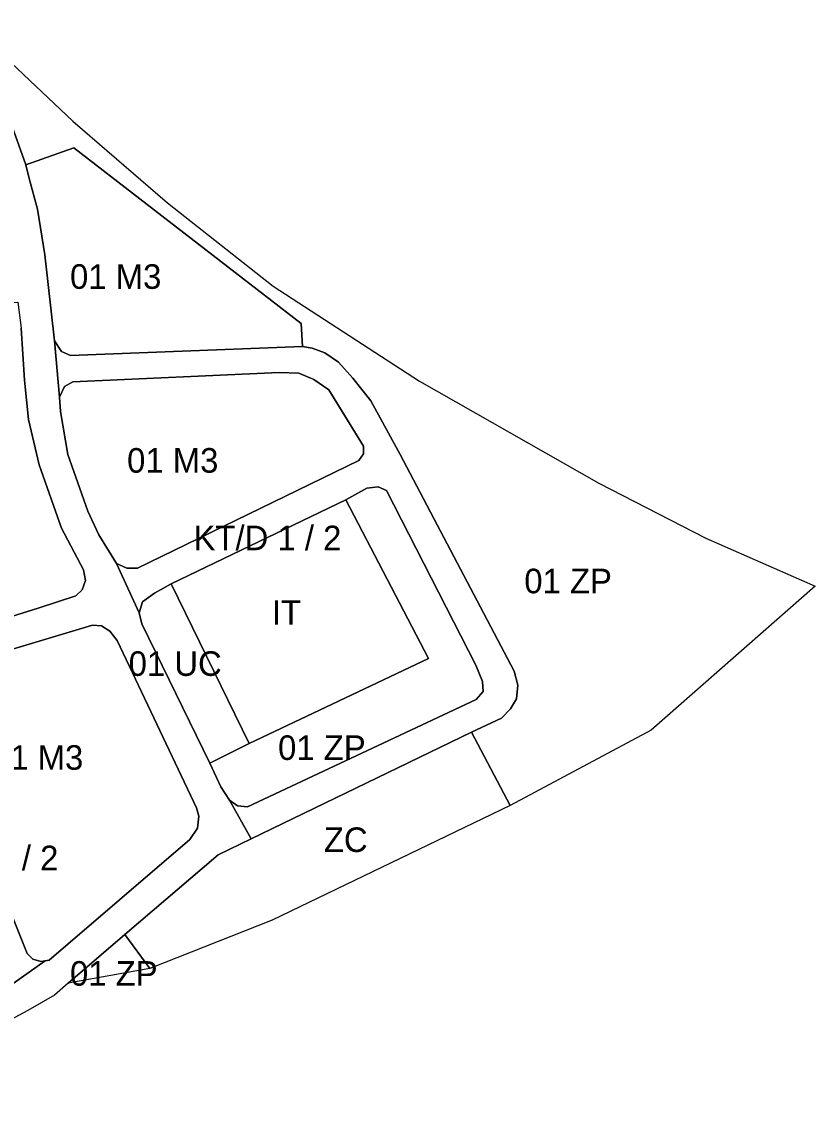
# Model space of a CAD drawing. Extents: x 7419295 to 7421535, y 5544294 to 5545394.
# Drawn here: x 7421212.4 to 7421535.3, y 5544388.6 to 5544834.1 of the extents above; entities that cross this region are included whole.
import ezdxf

# ---------------------------------------------------------------- set-up
doc = ezdxf.new("R2010")
doc.units = 0
doc.layers.add('linie_rozgraniczajace', color=7, linetype='Continuous')
doc.layers.add('oznaczenia_przeznaczen', color=7, linetype='Continuous')

msp = doc.modelspace()

# ---------------------------------------------------------------- linework, layer by layer
at = {"layer": 'linie_rozgraniczajace'}
for points in [[(7421190.2, 5544834.12), (7421233.16, 5544793.69), (7421271.62, 5544760.47), (7421314.64, 5544726.59), (7421374.27, 5544687.97), (7421447.31, 5544646.52), (7421490.78, 5544624.02), (7421535.28, 5544604.57), (7421468.56, 5544545.99), (7421411.16, 5544515.34), (7421395.36, 5544545.19), (7421407.68, 5544550.9), (7421411.34, 5544554.63), (7421413.72, 5544558.75), (7421414.29, 5544564.29), (7421412.78, 5544570.04), (7421366.31, 5544658.08), (7421354.46, 5544679.96), (7421347.09, 5544689.2), (7421341.26, 5544695.67), (7421335.7, 5544699.47), (7421330.54, 5544701.34), (7421326.62, 5544702), (7421326.08, 5544711.37), (7421233.6, 5544782.82), (7421214.02, 5544775.92), (7421200.76, 5544812.79)], [(7421200.76, 5544812.79), (7421214.02, 5544775.92), (7421215.32, 5544770.41), (7421218.69, 5544757.87), (7421221.67, 5544739.36), (7421225.6, 5544704.39), (7421227.66, 5544681.41), (7421228.05, 5544675.61), (7421231.15, 5544658.15), (7421239.24, 5544635.07), (7421243.76, 5544625.42), (7421250.91, 5544613.78), (7421260.12, 5544593.65), (7421261.25, 5544589.22), (7421288.83, 5544532.5), (7421293.35, 5544522.9), (7421296.9, 5544517.53), (7421305.77, 5544501.83), (7421292.24, 5544495.28), (7421254.34, 5544462.81), (7421231.17, 5544442.98), (7421225.65, 5544438.13), (7421214.78, 5544431.88), (7421134.24, 5544388.56)], [(7421186.73, 5544585.6), (7421218.96, 5544595.55), (7421234.34, 5544600.61), (7421236.91, 5544603.1), (7421238.34, 5544606.8), (7421237.43, 5544611.2), (7421228.5, 5544628.12), (7421219.45, 5544653.87), (7421215.06, 5544672.35), (7421213.44, 5544688.32), (7421212.1, 5544709.5)], [(7421203.12, 5544438.98), (7421221.82, 5544452.13), (7421223.48, 5544452.42), (7421280.78, 5544501.56), (7421283.93, 5544506.16), (7421284.37, 5544510.95), (7421283.44, 5544514.42), (7421251.11, 5544582.43), (7421248.25, 5544586.19), (7421244.82, 5544588.44), (7421241.15, 5544588.74), (7421193.57, 5544574.43)]]:
    msp.add_lwpolyline(points, dxfattribs=at)
for points in [[(7421214.02, 5544775.92), (7421233.6, 5544782.82), (7421326.08, 5544711.37), (7421326.62, 5544702), (7421232.2, 5544698.39), (7421228.48, 5544700.03), (7421225.6, 5544704.39), (7421221.67, 5544739.36), (7421218.69, 5544757.87), (7421215.32, 5544770.41)], [(7421210.76, 5544720.11), (7421212.1, 5544709.5), (7421213.44, 5544688.32), (7421215.06, 5544672.35), (7421219.45, 5544653.87), (7421228.5, 5544628.12), (7421237.43, 5544611.2), (7421238.34, 5544606.8), (7421236.91, 5544603.1), (7421234.34, 5544600.61), (7421218.96, 5544595.55), (7421186.73, 5544585.6), (7421170.98, 5544582.34), (7421159.54, 5544616.11), (7421149.43, 5544626.06), (7421116.42, 5544643.66), (7421034.62, 5544653.87), (7421009.98, 5544649.77), (7421000.75, 5544682.83), (7421016.84, 5544686.9), (7421014.51, 5544696.59), (7421105.89, 5544713.01)], [(7421225.6, 5544704.39), (7421228.48, 5544700.03), (7421232.2, 5544698.39), (7421326.62, 5544702), (7421330.54, 5544701.34), (7421335.7, 5544699.47), (7421341.26, 5544695.67), (7421347.09, 5544689.2), (7421354.46, 5544679.96), (7421366.31, 5544658.08), (7421412.78, 5544570.04), (7421414.29, 5544564.29), (7421413.72, 5544558.75), (7421411.34, 5544554.63), (7421407.68, 5544550.9), (7421395.36, 5544545.19), (7421305.77, 5544501.83), (7421296.9, 5544517.53), (7421300.18, 5544515.13), (7421304.25, 5544514.73), (7421397.29, 5544558.43), (7421400.18, 5544561.67), (7421399.85, 5544565.83), (7421397.2, 5544572.43), (7421360.78, 5544643.5), (7421357.38, 5544645.01), (7421352.8, 5544644.37), (7421344.25, 5544639.7), (7421273.15, 5544605.51), (7421266.31, 5544601.65), (7421261.52, 5544598.18), (7421260.12, 5544593.65), (7421250.91, 5544613.78), (7421255.12, 5544611.86), (7421259.41, 5544611.89), (7421349.52, 5544655.65), (7421351.47, 5544658.41), (7421351.46, 5544661.55), (7421337.34, 5544684.38), (7421331.29, 5544688.61), (7421325.14, 5544691.19), (7421317.18, 5544691.46), (7421233.12, 5544687.75), (7421229.7, 5544685.82), (7421227.66, 5544681.41)], [(7421227.66, 5544681.41), (7421229.7, 5544685.82), (7421233.12, 5544687.75), (7421317.18, 5544691.46), (7421325.14, 5544691.19), (7421331.29, 5544688.61), (7421337.34, 5544684.38), (7421351.46, 5544661.55), (7421351.47, 5544658.41), (7421349.52, 5544655.65), (7421259.41, 5544611.89), (7421255.12, 5544611.86), (7421250.91, 5544613.78), (7421243.76, 5544625.42), (7421239.24, 5544635.07), (7421231.15, 5544658.15), (7421228.05, 5544675.61)], [(7421344.25, 5544639.7), (7421352.8, 5544644.37), (7421357.38, 5544645.01), (7421360.78, 5544643.5), (7421397.2, 5544572.43), (7421399.85, 5544565.83), (7421400.18, 5544561.67), (7421397.29, 5544558.43), (7421304.25, 5544514.73), (7421300.18, 5544515.13), (7421296.9, 5544517.53), (7421293.35, 5544522.9), (7421288.83, 5544532.5), (7421304.87, 5544540.61), (7421377.86, 5544575.17)], [(7421344.25, 5544639.7), (7421377.86, 5544575.17), (7421304.87, 5544540.61), (7421273.15, 5544605.51)], [(7421273.15, 5544605.51), (7421304.87, 5544540.61), (7421288.83, 5544532.5), (7421261.25, 5544589.22), (7421260.12, 5544593.65), (7421261.52, 5544598.18), (7421266.31, 5544601.65)], [(7421173.61, 5544569.95), (7421177.84, 5544571.46), (7421193.57, 5544574.43), (7421241.15, 5544588.74), (7421244.82, 5544588.44), (7421248.25, 5544586.19), (7421251.11, 5544582.43), (7421283.44, 5544514.42), (7421284.37, 5544510.95), (7421283.93, 5544506.16), (7421280.78, 5544501.56), (7421223.48, 5544452.42), (7421221.82, 5544452.13), (7421220.16, 5544451.84), (7421216.79, 5544452.75), (7421214.51, 5544455.18), (7421170.83, 5544563.87), (7421171.32, 5544567.47)], [(7421173.61, 5544569.95), (7421171.32, 5544567.47), (7421170.83, 5544563.87), (7421214.51, 5544455.18), (7421216.79, 5544452.75), (7421220.16, 5544451.84), (7421221.82, 5544452.13), (7421203.12, 5544438.98), (7421206.52, 5544445.23), (7421205.58, 5544449), (7421163.14, 5544554.61), (7421160.48, 5544561.63), (7421157.65, 5544564.79), (7421156.21, 5544565.11)], [(7421395.36, 5544545.19), (7421411.16, 5544515.34), (7421314.26, 5544468.66), (7421264.47, 5544448.95), (7421254.34, 5544462.81), (7421292.24, 5544495.28), (7421305.77, 5544501.83)], [(7421254.34, 5544462.81), (7421264.47, 5544448.95), (7421231.17, 5544442.98)]]:
    msp.add_lwpolyline(points, close=True, dxfattribs=at)

# ---------------------------------------------------------------- texts
at = {"layer": 'oznaczenia_przeznaczen'}
for s, p in [('01 M3', (7421231.99, 5544725.52)), ('01 M3', (7421255.21, 5544650.73)), ('KT/D 1 / 2', (7421282.25, 5544619.18)), ('01 ZP', (7421416.9, 5544601.66)), ('IT', (7421314.14, 5544588.85)), ('01 UC', (7421255.85, 5544568.06)), ('01 M3', (7421200.21, 5544529.86)), ('01 ZP', (7421316.67, 5544533.86)), ('ZC', (7421335.31, 5544496.41)), ('KT/D 1 / 2', (7421167.05, 5544488.99)), ('01 ZP', (7421231.97, 5544442.01))]:
    msp.add_text(s, height=10, dxfattribs=at).set_placement(p)

doc.saveas('drawing.dxf')
